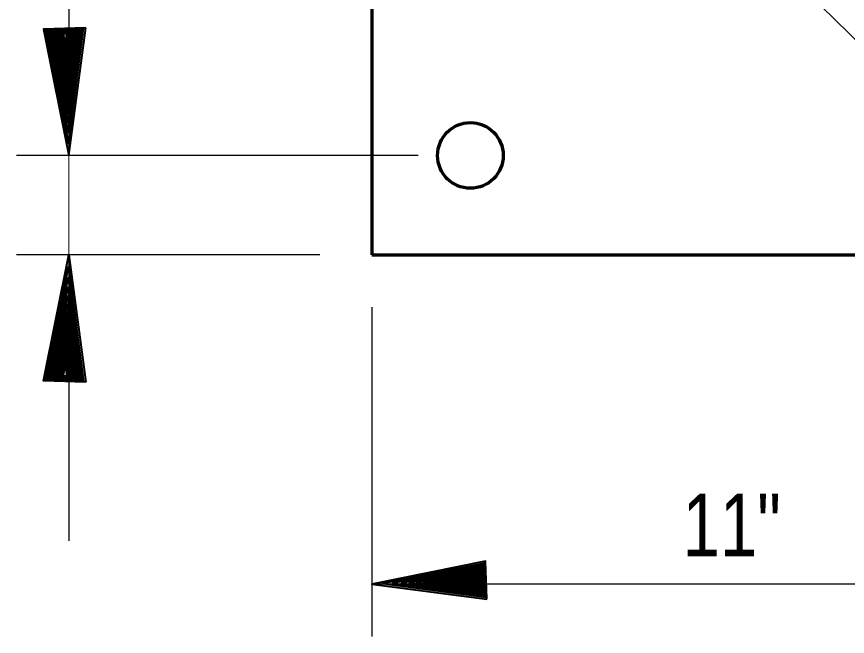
# Model space of a CAD drawing. Extents: x 895.6 to 930.4, y -2278.6 to -2254.7.
# Drawn here: x 901.144 to 902.847, y -2262.172 to -2260.903 of the extents above; entities that cross this region are included whole.
import ezdxf

# ---------------------------------------------------------------- set-up
doc = ezdxf.new("R2010")
doc.units = 0
doc.header["$LTSCALE"] = 0.051
doc.layers.add('1', color=7, linetype='Continuous', lineweight=70)
doc.layers.add('3', color=7, linetype='Continuous', lineweight=40)

msp = doc.modelspace()

# ---------------------------------------------------------------- hatches: boundary and pattern name
at = {"layer": '3'}
for points in [[(901.286, -2260.92608), (901.19933, -2260.929), (901.2515, -2261.18742), (901.2515, -2261.18742)], [(901.28167, -2260.92733), (901.20367, -2260.93008), (901.25067, -2261.16267), (901.25067, -2261.16267)], [(901.27775, -2260.92858), (901.20767, -2260.93092), (901.24992, -2261.14025), (901.24992, -2261.14025)], [(901.27433, -2260.92958), (901.21125, -2260.93175), (901.24925, -2261.12025), (901.24925, -2261.12025)], [(901.27133, -2260.9305), (901.2145, -2260.93242), (901.24867, -2261.10217), (901.24867, -2261.10217)], [(901.26842, -2260.93158), (901.21733, -2260.93317), (901.24817, -2261.08592), (901.24817, -2261.08592)], [(901.26583, -2260.93225), (901.21992, -2260.93375), (901.24767, -2261.07117), (901.24767, -2261.07117)], [(901.26367, -2260.93308), (901.22217, -2260.93433), (901.24717, -2261.05792), (901.24717, -2261.05792)], [(901.26167, -2260.9335), (901.22425, -2260.93483), (901.24667, -2261.04617), (901.24667, -2261.04617)], [(901.25967, -2260.93425), (901.226, -2260.93542), (901.24633, -2261.03533), (901.24633, -2261.03533)], [(901.25817, -2260.93467), (901.22783, -2260.93575), (901.24608, -2261.02575), (901.24608, -2261.02575)], [(901.25658, -2260.93517), (901.22942, -2260.93617), (901.24567, -2261.01717), (901.24567, -2261.01717)], [(901.25525, -2260.93558), (901.23075, -2260.93642), (901.24542, -2261.00925), (901.24542, -2261.00925)], [(901.254, -2260.93617), (901.23192, -2260.93667), (901.24525, -2261.00233), (901.24525, -2261.00233)], [(901.25292, -2260.93633), (901.23308, -2260.937), (901.24508, -2260.99608), (901.24508, -2260.99608)], [(901.25192, -2260.93675), (901.23408, -2260.93717), (901.24475, -2260.99042), (901.24475, -2260.99042)], [(901.251, -2260.93692), (901.23492, -2260.9375), (901.24458, -2260.98533), (901.24458, -2260.98533)], [(901.25017, -2260.93708), (901.23575, -2260.93767), (901.24442, -2260.98075), (901.24442, -2260.98075)], [(901.24975, -2260.9375), (901.23658, -2260.93775), (901.24442, -2260.97667), (901.24442, -2260.97667)], [(901.24917, -2260.93767), (901.23733, -2260.93808), (901.24433, -2260.973), (901.24433, -2260.973)], [(901.24867, -2260.938), (901.23808, -2260.93842), (901.2445, -2260.96975), (901.2445, -2260.96975)], [(901.24808, -2260.938), (901.23867, -2260.93842), (901.24433, -2260.96667), (901.24433, -2260.96667)], [(901.24758, -2260.93817), (901.23908, -2260.9385), (901.24408, -2260.96392), (901.24408, -2260.96392)], [(901.24717, -2260.93842), (901.23958, -2260.93858), (901.24417, -2260.96158), (901.24417, -2260.96158)], [(901.286, -2261.65192), (901.19933, -2261.649), (901.2515, -2261.39058), (901.2515, -2261.39058)], [(901.28167, -2261.65067), (901.20367, -2261.64792), (901.25067, -2261.41533), (901.25067, -2261.41533)], [(901.27775, -2261.64942), (901.20767, -2261.64708), (901.24992, -2261.43775), (901.24992, -2261.43775)], [(901.27433, -2261.64842), (901.21125, -2261.64625), (901.24925, -2261.45775), (901.24925, -2261.45775)], [(901.27133, -2261.6475), (901.2145, -2261.64558), (901.24867, -2261.47583), (901.24867, -2261.47583)], [(901.26842, -2261.64642), (901.21733, -2261.64483), (901.24817, -2261.49208), (901.24817, -2261.49208)], [(901.26583, -2261.64575), (901.21992, -2261.64425), (901.24767, -2261.50683), (901.24767, -2261.50683)], [(901.26367, -2261.64492), (901.22217, -2261.64367), (901.24717, -2261.52008), (901.24717, -2261.52008)], [(901.26167, -2261.6445), (901.22425, -2261.64317), (901.24667, -2261.53183), (901.24667, -2261.53183)], [(901.25967, -2261.64375), (901.226, -2261.64258), (901.24633, -2261.54267), (901.24633, -2261.54267)], [(901.25817, -2261.64333), (901.22783, -2261.64225), (901.24608, -2261.55225), (901.24608, -2261.55225)], [(901.25658, -2261.64283), (901.22942, -2261.64183), (901.24567, -2261.56083), (901.24567, -2261.56083)], [(901.25525, -2261.64242), (901.23075, -2261.64158), (901.24542, -2261.56875), (901.24542, -2261.56875)], [(901.254, -2261.64183), (901.23192, -2261.64133), (901.24525, -2261.57567), (901.24525, -2261.57567)], [(901.25292, -2261.64167), (901.23308, -2261.641), (901.24508, -2261.58192), (901.24508, -2261.58192)], [(901.25192, -2261.64125), (901.23408, -2261.64083), (901.24475, -2261.58758), (901.24475, -2261.58758)], [(901.251, -2261.64108), (901.23492, -2261.6405), (901.24458, -2261.59267), (901.24458, -2261.59267)], [(901.25017, -2261.64092), (901.23575, -2261.64033), (901.24442, -2261.59725), (901.24442, -2261.59725)], [(901.24975, -2261.6405), (901.23658, -2261.64025), (901.24442, -2261.60133), (901.24442, -2261.60133)], [(901.24917, -2261.64033), (901.23733, -2261.63992), (901.24433, -2261.605), (901.24433, -2261.605)], [(901.24867, -2261.64), (901.23808, -2261.63958), (901.2445, -2261.60825), (901.2445, -2261.60825)], [(901.24808, -2261.64), (901.23867, -2261.63958), (901.24433, -2261.61133), (901.24433, -2261.61133)], [(901.24758, -2261.63983), (901.23908, -2261.6395), (901.24408, -2261.61408), (901.24408, -2261.61408)], [(901.24717, -2261.63958), (901.23958, -2261.63942), (901.24417, -2261.61642), (901.24417, -2261.61642)], [(902.108, -2262.09608), (902.10533, -2262.01808), (901.87267, -2262.065), (901.87267, -2262.065)], [(902.10675, -2262.09217), (902.10442, -2262.022), (901.89508, -2262.06417), (901.89508, -2262.06417)], [(902.10575, -2262.08867), (902.10358, -2262.02558), (901.91517, -2262.06358), (901.91517, -2262.06358)], [(902.10475, -2262.08558), (902.10283, -2262.02883), (901.93325, -2262.063), (901.93325, -2262.063)], [(902.104, -2262.08292), (902.10217, -2262.03175), (901.9495, -2262.0625), (901.9495, -2262.0625)], [(902.103, -2262.08025), (902.1015, -2262.03425), (901.96417, -2262.062), (901.96417, -2262.062)], [(902.10242, -2262.07792), (902.10108, -2262.0365), (901.97733, -2262.0615), (901.97733, -2262.0615)], [(902.10167, -2262.076), (902.10058, -2262.03867), (901.98933, -2262.06117), (901.98933, -2262.06117)], [(902.10133, -2262.07417), (902.1, -2262.0405), (901.99992, -2262.06067), (901.99992, -2262.06067)], [(902.10067, -2262.07242), (902.09958, -2262.04208), (902.00958, -2262.06042), (902.00958, -2262.06042)], [(902.10017, -2262.07092), (902.09925, -2262.04375), (902.01825, -2262.06008), (902.01825, -2262.06008)], [(902.09983, -2262.0695), (902.09892, -2262.04517), (902.026, -2262.05975), (902.026, -2262.05975)], [(902.09933, -2262.06842), (902.09867, -2262.04633), (902.03317, -2262.05958), (902.03317, -2262.05958)], [(902.09892, -2262.06725), (902.09842, -2262.04742), (902.03925, -2262.05942), (902.03925, -2262.05942)], [(902.09867, -2262.06633), (902.09808, -2262.04842), (902.045, -2262.05925), (902.045, -2262.05925)], [(902.09842, -2262.06542), (902.098, -2262.04925), (902.05008, -2262.05892), (902.05008, -2262.05892)], [(902.09817, -2262.06458), (902.09767, -2262.05), (902.05467, -2262.05875), (902.05467, -2262.05875)], [(902.098, -2262.06383), (902.09758, -2262.05083), (902.05875, -2262.05867), (902.05875, -2262.05867)], [(902.09767, -2262.06342), (902.09742, -2262.05158), (902.06242, -2262.05867), (902.06242, -2262.05867)], [(902.0975, -2262.06283), (902.09717, -2262.05225), (902.06567, -2262.05858), (902.06567, -2262.05858)], [(902.09725, -2262.0625), (902.09692, -2262.05292), (902.06867, -2262.05875), (902.06867, -2262.05875)], [(902.09725, -2262.06192), (902.09692, -2262.05342), (902.07142, -2262.05858), (902.07142, -2262.05858)], [(902.09708, -2262.06142), (902.09675, -2262.05383), (902.07383, -2262.05833), (902.07383, -2262.05833)], [(902.09692, -2262.06117), (902.09667, -2262.05433), (902.076, -2262.05842), (902.076, -2262.05842)]]:
    msp.add_hatch(color=256, dxfattribs=at).paths.add_polyline_path(points)

# ---------------------------------------------------------------- linework, layer by layer
at = {"layer": '1'}
for p, q in [((901.87267, -2258.93683), (901.87267, -2261.39058)), ((901.87267, -2261.39058), (903.35208, -2261.39058))]:
    msp.add_line(p, q, dxfattribs=at)
at = {"layer": '1', "lineweight": 25}
for p, q in [((901.2515, -2260.54125), (901.2515, -2261.18742)), ((901.96708, -2261.18742), (901.14425, -2261.18742)), ((901.76542, -2261.39058), (901.14425, -2261.39058)), ((901.2515, -2261.39058), (901.2515, -2261.97625)), ((901.87267, -2261.498), (901.87267, -2262.17225)), ((903.35208, -2262.065), (901.87267, -2262.065))]:
    msp.add_line(p, q, dxfattribs=at)
at = {"layer": '1', "lineweight": 13}
msp.add_line((901.2515, -2261.18742), (901.2515, -2261.8335), dxfattribs=at)
at = {"layer": '1', "lineweight": 25}
msp.add_lwpolyline([(903.93533, -2261.75933), (903.69333, -2261.75933), (902.12517, -2260.229), (902.2195, -2260.3485), (902.24942, -2260.31692), (902.12517, -2260.229)], dxfattribs=at)
at = {"layer": '1'}
msp.add_circle((902.07433, -2261.18735), 0.06722, dxfattribs=at)
at = {"layer": '3'}
for points in [[(901.286, -2260.92608), (901.19933, -2260.929), (901.2515, -2261.18742), (901.2515, -2261.18742)], [(901.28167, -2260.92733), (901.20367, -2260.93008), (901.25067, -2261.16267), (901.25067, -2261.16267)], [(901.27775, -2260.92858), (901.20767, -2260.93092), (901.24992, -2261.14025), (901.24992, -2261.14025)], [(901.27433, -2260.92958), (901.21125, -2260.93175), (901.24925, -2261.12025), (901.24925, -2261.12025)], [(901.27133, -2260.9305), (901.2145, -2260.93242), (901.24867, -2261.10217), (901.24867, -2261.10217)], [(901.26842, -2260.93158), (901.21733, -2260.93317), (901.24817, -2261.08592), (901.24817, -2261.08592)], [(901.26583, -2260.93225), (901.21992, -2260.93375), (901.24767, -2261.07117), (901.24767, -2261.07117)], [(901.26367, -2260.93308), (901.22217, -2260.93433), (901.24717, -2261.05792), (901.24717, -2261.05792)], [(901.26167, -2260.9335), (901.22425, -2260.93483), (901.24667, -2261.04617), (901.24667, -2261.04617)], [(901.25967, -2260.93425), (901.226, -2260.93542), (901.24633, -2261.03533), (901.24633, -2261.03533)], [(901.25817, -2260.93467), (901.22783, -2260.93575), (901.24608, -2261.02575), (901.24608, -2261.02575)], [(901.25658, -2260.93517), (901.22942, -2260.93617), (901.24567, -2261.01717), (901.24567, -2261.01717)], [(901.25525, -2260.93558), (901.23075, -2260.93642), (901.24542, -2261.00925), (901.24542, -2261.00925)], [(901.254, -2260.93617), (901.23192, -2260.93667), (901.24525, -2261.00233), (901.24525, -2261.00233)], [(901.25292, -2260.93633), (901.23308, -2260.937), (901.24508, -2260.99608), (901.24508, -2260.99608)], [(901.25192, -2260.93675), (901.23408, -2260.93717), (901.24475, -2260.99042), (901.24475, -2260.99042)], [(901.251, -2260.93692), (901.23492, -2260.9375), (901.24458, -2260.98533), (901.24458, -2260.98533)], [(901.25017, -2260.93708), (901.23575, -2260.93767), (901.24442, -2260.98075), (901.24442, -2260.98075)], [(901.24975, -2260.9375), (901.23658, -2260.93775), (901.24442, -2260.97667), (901.24442, -2260.97667)], [(901.24917, -2260.93767), (901.23733, -2260.93808), (901.24433, -2260.973), (901.24433, -2260.973)], [(901.24867, -2260.938), (901.23808, -2260.93842), (901.2445, -2260.96975), (901.2445, -2260.96975)], [(901.24808, -2260.938), (901.23867, -2260.93842), (901.24433, -2260.96667), (901.24433, -2260.96667)], [(901.24758, -2260.93817), (901.23908, -2260.9385), (901.24408, -2260.96392), (901.24408, -2260.96392)], [(901.24717, -2260.93842), (901.23958, -2260.93858), (901.24417, -2260.96158), (901.24417, -2260.96158)], [(901.286, -2261.65192), (901.19933, -2261.649), (901.2515, -2261.39058), (901.2515, -2261.39058)], [(901.28167, -2261.65067), (901.20367, -2261.64792), (901.25067, -2261.41533), (901.25067, -2261.41533)], [(901.27775, -2261.64942), (901.20767, -2261.64708), (901.24992, -2261.43775), (901.24992, -2261.43775)], [(901.27433, -2261.64842), (901.21125, -2261.64625), (901.24925, -2261.45775), (901.24925, -2261.45775)], [(901.27133, -2261.6475), (901.2145, -2261.64558), (901.24867, -2261.47583), (901.24867, -2261.47583)], [(901.26842, -2261.64642), (901.21733, -2261.64483), (901.24817, -2261.49208), (901.24817, -2261.49208)], [(901.26583, -2261.64575), (901.21992, -2261.64425), (901.24767, -2261.50683), (901.24767, -2261.50683)], [(901.26367, -2261.64492), (901.22217, -2261.64367), (901.24717, -2261.52008), (901.24717, -2261.52008)], [(901.26167, -2261.6445), (901.22425, -2261.64317), (901.24667, -2261.53183), (901.24667, -2261.53183)], [(901.25967, -2261.64375), (901.226, -2261.64258), (901.24633, -2261.54267), (901.24633, -2261.54267)], [(901.25817, -2261.64333), (901.22783, -2261.64225), (901.24608, -2261.55225), (901.24608, -2261.55225)], [(901.25658, -2261.64283), (901.22942, -2261.64183), (901.24567, -2261.56083), (901.24567, -2261.56083)], [(901.25525, -2261.64242), (901.23075, -2261.64158), (901.24542, -2261.56875), (901.24542, -2261.56875)], [(901.254, -2261.64183), (901.23192, -2261.64133), (901.24525, -2261.57567), (901.24525, -2261.57567)], [(901.25292, -2261.64167), (901.23308, -2261.641), (901.24508, -2261.58192), (901.24508, -2261.58192)], [(901.25192, -2261.64125), (901.23408, -2261.64083), (901.24475, -2261.58758), (901.24475, -2261.58758)], [(901.251, -2261.64108), (901.23492, -2261.6405), (901.24458, -2261.59267), (901.24458, -2261.59267)], [(901.25017, -2261.64092), (901.23575, -2261.64033), (901.24442, -2261.59725), (901.24442, -2261.59725)], [(901.24975, -2261.6405), (901.23658, -2261.64025), (901.24442, -2261.60133), (901.24442, -2261.60133)], [(901.24917, -2261.64033), (901.23733, -2261.63992), (901.24433, -2261.605), (901.24433, -2261.605)], [(901.24867, -2261.64), (901.23808, -2261.63958), (901.2445, -2261.60825), (901.2445, -2261.60825)], [(901.24808, -2261.64), (901.23867, -2261.63958), (901.24433, -2261.61133), (901.24433, -2261.61133)], [(901.24758, -2261.63983), (901.23908, -2261.6395), (901.24408, -2261.61408), (901.24408, -2261.61408)], [(901.24717, -2261.63958), (901.23958, -2261.63942), (901.24417, -2261.61642), (901.24417, -2261.61642)], [(902.108, -2262.09608), (902.10533, -2262.01808), (901.87267, -2262.065), (901.87267, -2262.065)], [(902.10675, -2262.09217), (902.10442, -2262.022), (901.89508, -2262.06417), (901.89508, -2262.06417)], [(902.10575, -2262.08867), (902.10358, -2262.02558), (901.91517, -2262.06358), (901.91517, -2262.06358)], [(902.10475, -2262.08558), (902.10283, -2262.02883), (901.93325, -2262.063), (901.93325, -2262.063)], [(902.104, -2262.08292), (902.10217, -2262.03175), (901.9495, -2262.0625), (901.9495, -2262.0625)], [(902.103, -2262.08025), (902.1015, -2262.03425), (901.96417, -2262.062), (901.96417, -2262.062)], [(902.10242, -2262.07792), (902.10108, -2262.0365), (901.97733, -2262.0615), (901.97733, -2262.0615)], [(902.10167, -2262.076), (902.10058, -2262.03867), (901.98933, -2262.06117), (901.98933, -2262.06117)], [(902.10133, -2262.07417), (902.1, -2262.0405), (901.99992, -2262.06067), (901.99992, -2262.06067)], [(902.10067, -2262.07242), (902.09958, -2262.04208), (902.00958, -2262.06042), (902.00958, -2262.06042)], [(902.10017, -2262.07092), (902.09925, -2262.04375), (902.01825, -2262.06008), (902.01825, -2262.06008)], [(902.09983, -2262.0695), (902.09892, -2262.04517), (902.026, -2262.05975), (902.026, -2262.05975)], [(902.09933, -2262.06842), (902.09867, -2262.04633), (902.03317, -2262.05958), (902.03317, -2262.05958)], [(902.09892, -2262.06725), (902.09842, -2262.04742), (902.03925, -2262.05942), (902.03925, -2262.05942)], [(902.09867, -2262.06633), (902.09808, -2262.04842), (902.045, -2262.05925), (902.045, -2262.05925)], [(902.09842, -2262.06542), (902.098, -2262.04925), (902.05008, -2262.05892), (902.05008, -2262.05892)], [(902.09817, -2262.06458), (902.09767, -2262.05), (902.05467, -2262.05875), (902.05467, -2262.05875)], [(902.098, -2262.06383), (902.09758, -2262.05083), (902.05875, -2262.05867), (902.05875, -2262.05867)], [(902.09767, -2262.06342), (902.09742, -2262.05158), (902.06242, -2262.05867), (902.06242, -2262.05867)], [(902.0975, -2262.06283), (902.09717, -2262.05225), (902.06567, -2262.05858), (902.06567, -2262.05858)], [(902.09725, -2262.0625), (902.09692, -2262.05292), (902.06867, -2262.05875), (902.06867, -2262.05875)], [(902.09725, -2262.06192), (902.09692, -2262.05342), (902.07142, -2262.05858), (902.07142, -2262.05858)], [(902.09708, -2262.06142), (902.09675, -2262.05383), (902.07383, -2262.05833), (902.07383, -2262.05833)], [(902.09692, -2262.06117), (902.09667, -2262.05433), (902.076, -2262.05842), (902.076, -2262.05842)]]:
    msp.add_lwpolyline(points, close=True, dxfattribs=at)

# ---------------------------------------------------------------- texts
at = {"layer": '1', "width": 0.8}
msp.add_text('11"', height=0.1286, dxfattribs=at).set_placement((902.50908, -2262.00842))

doc.saveas('drawing.dxf')
